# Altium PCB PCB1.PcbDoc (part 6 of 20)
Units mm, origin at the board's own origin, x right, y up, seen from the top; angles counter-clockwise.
Board outline 294.51 x 138.18 mm, 12 copper layers (Top Layer 1 _Signal, L2_GND, L3_Signals, L4_GND, L5_POWER, L6_Signals, L7_GND, L8_Signals, L9_GND, L10_POWER, L11_GND, Bottom Layer_Signals), stack 1.788 mm thick; 1254 components, 836 nets, 5699 pads, 2073 vias.
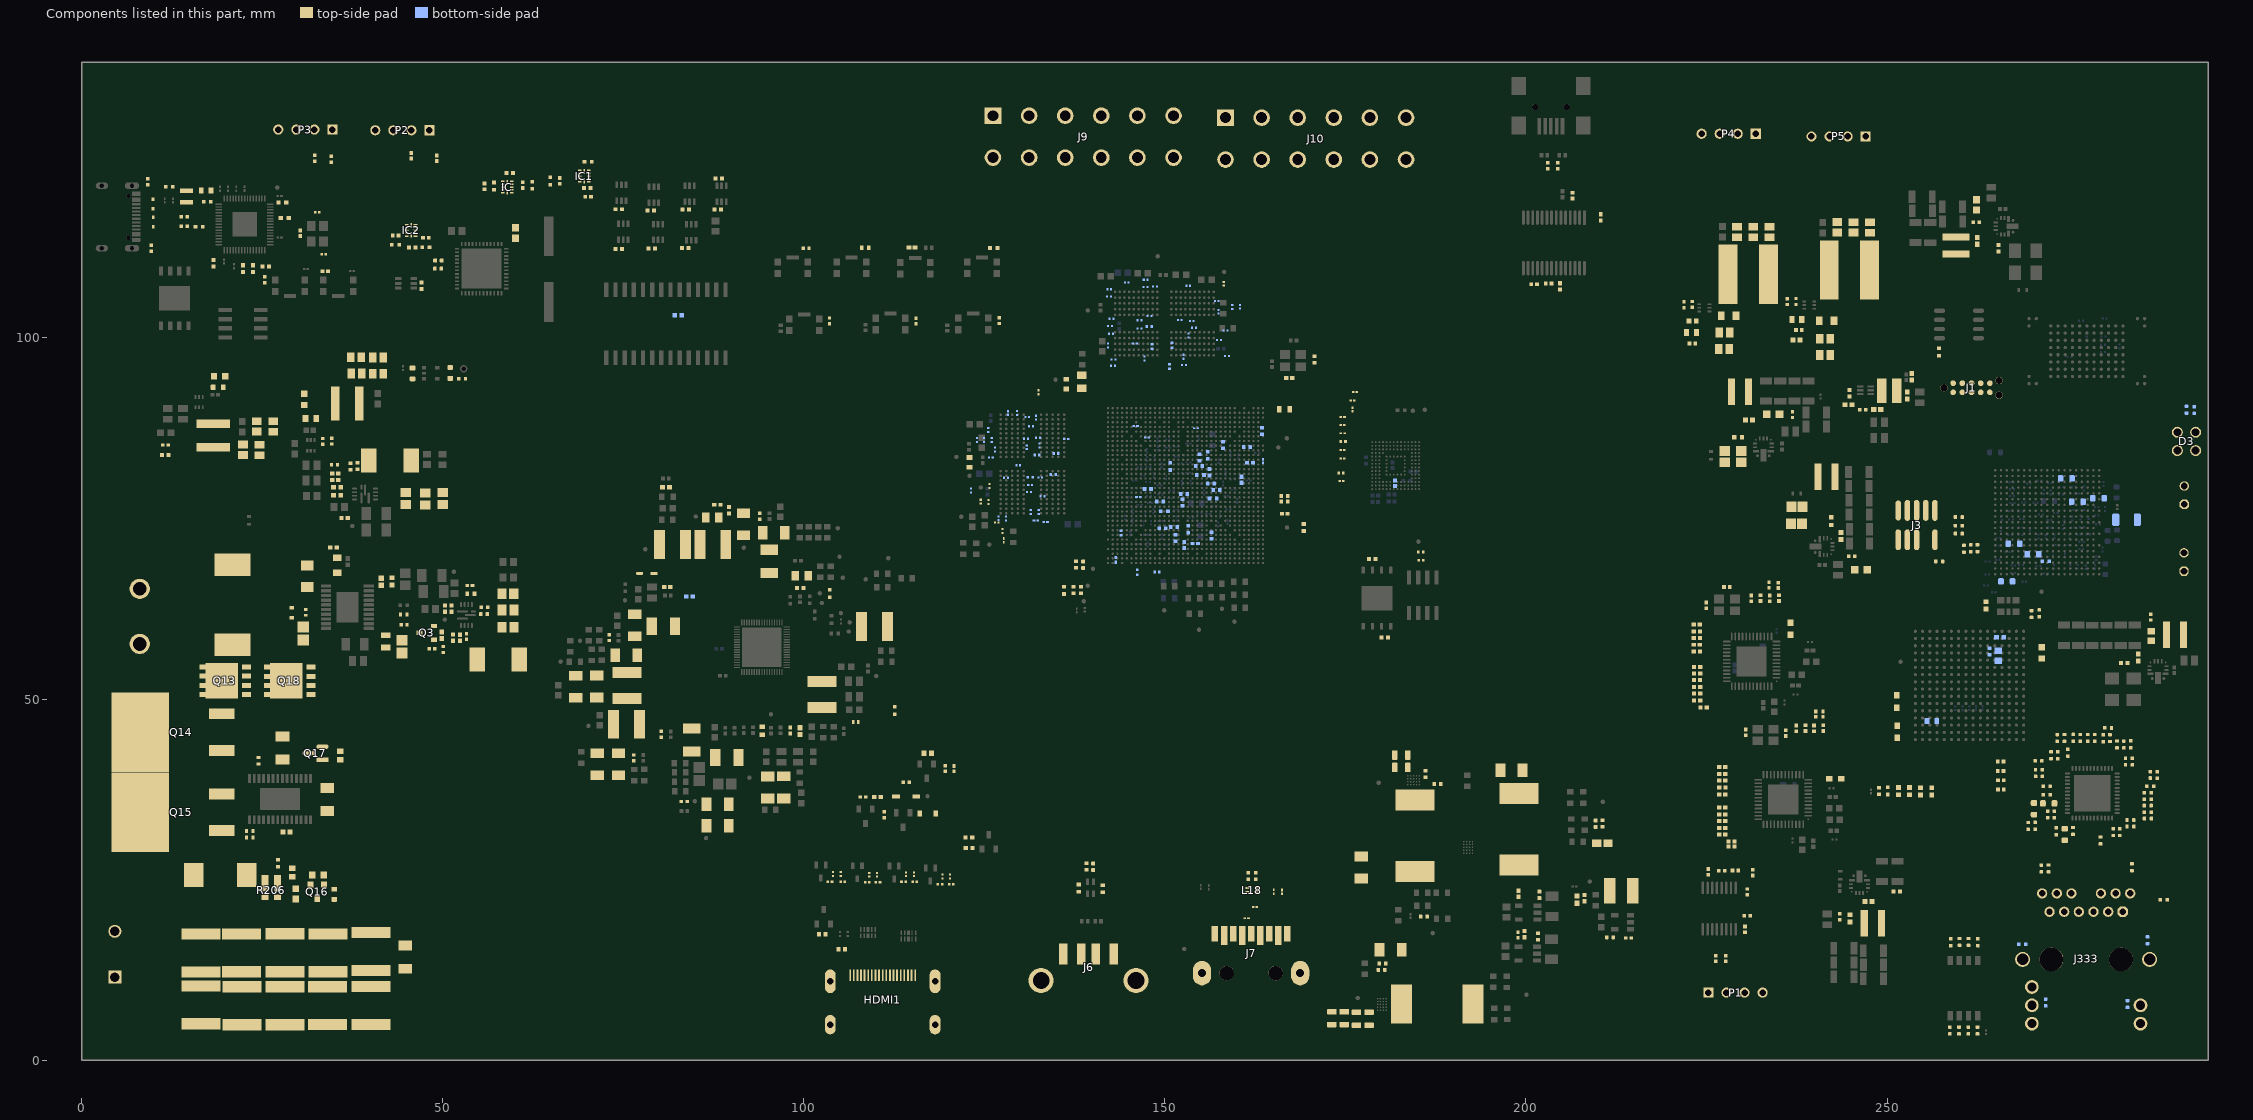
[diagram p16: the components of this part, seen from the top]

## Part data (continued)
C217: library part CMP-001-00011-6, "Chip Capacitor, 10 pF, +/- 0.25 pF, 50 V, 0402 (1005 Metric)", Capacitor Type=Ceramic, Case/Package=0402, Max Operating Temperature=125°C, Min Operating Temperature=-55°C, Tolerance=0.25%, Voltage Rating=50V
C218: library part CMP-2008-03481-1, "C0402C121G5GACTU", Manufacturer=Kemet
C219: library part CMP-2007-04689-1, Manufacturer="AVX Interconnect / Elco"
C220 C221 C230 C231 C232 C233 C249 C251 C252 C262 C263 C271 C272 C283 C289 C304 C309 C611 C627: library part CMP-001-00074-3, "10uF 6.3V X5R ±20% 0402 Multilayer Ceramic Capacitors MLCC - SMD/SMT ROHS", Case/Package=0402, LCSC=C76991, Max Operating Temperature=85°C, Min Operating Temperature=-55°C, Tolerance=10%, Voltage Rating=6.3V
C222 C239 C255 C264 C276 C306 C311 C463 C467 C542 C561 C567 C628: library part CMP-03422-000823-1, "10V 4.7uF X5R ±10% 0402 Multilayer Ceramic Capacitors MLCC - SMD/SMT ROHS", Capacitance="4.7 uF", LCSC=C326586, Manufacturer=YAGEO, Manufacturer Part Number=CC0402KRX5R6BB475, Package=CC0402, Temperature="-55°C to +125°C", Temperature Characteristic=X5R, Temperature Coefficient=30ppm/°C, Temperature Range High=+125°C, Temperature Range Low=-55°C, Tolerance=0.1, Voltage Rating="10 V"
C225: library part CMP-06035-026840-2, "CERAMIC CAP, MLCC 1UF 50VDC X5R"
C313 C369 C370 C371 C372 C374 C375 C376 C377 C378 C380 C381 C382 C383 C384 C385 C387 C389 C391: library part CAP1463, Manufacturer 1="TDK Corporation", Manufacturer 2="Taiyo Yuden", Manufacturer 3=Murata, Manufacturer 4=Yageo, Manufacturer Part Number 1=C1005X7R1H104K050BB, Manufacturer Part Number 2=UMK105B7104KV-FR, Manufacturer Part Number 3=GRM155R71H104KE14D, Manufacturer Part Number 4=CC0402KRX7R9BB104, Operating Temperature="-55C to +125C", Package=0402, Supplier Part Number 1=445-5932-1-ND, Temperature Coefficient=X7R, Tolerance=10%, Voltage=50V
C317 C318 C319 C320 C322 C323 C324 C327 C328 C331 C332 C333 C334 C335 C336 C337 C342 C344 C345 C346 C356 C357 C358 C359 C360 C361 C362 C363 C364 C365 C395 C396 C397 C398 C399 C400 C401 C403 C404 C405 C406 C407 C408 C409 C410 C411 C416 C417 C418 C419 C420 C421 C422 C423 C424 C425 C426 C427 C428 C429: library part CMP-03422-000955-1, "CC0201 100 nF X5R 20.00% 10 V", Capacitance="100 nF", Manufacturer=Yageo, Manufacturer Part Number=CC0201MRX5R6BB104, Package=CC0201-BA, Temperature="-55°C to +85°C", Temperature Characteristic=X5R, Temperature Coefficient=15%, Temperature Range High=+85°C, Temperature Range Low=-55°C, Tolerance=0.2, Voltage Rating="10 V"
C343 C352 C437 C488: library part CMP-06035-039918-1, "Chip Multilayer Ceramic Capacitors for General Purpose, 0805, 22uF, X5R, 15%, 20%, 10V / GRM21BR61A226ME44L", Capacitance=22uF, Case Code (Imperial)=0805, Case Code (Metric)=2012, Dielectric=X5R, Dielectric Material=Ceramic, Max Operating Temperature=85°C, Min Operating Temperature=-55°C, Package Quantity=3000, Tolerance=20%, Voltage=10V
C349 C351 C604 C605: library part CMP-08246-006695-1, "Multilayer Ceramic Capacitors 6.8μF ±10% 35V X5R SMD 0805 / C2012X5R1V685K125AC", Capacitance=6.8uF, Case Code (Imperial)=0805, Case Code (Metric)=2012, Dielectric Material=Ceramic, Max Operating Temperature=85°C, Min Operating Temperature=-55°C, Package Quantity=2000, Tolerance=10%, Voltage Rating=35V
C355: library part CMP-2008-04611-1, "GRM155R71C563KA88D", Manufacturer=Murata
C373 C379 C386 C390: library part CAP1207, Manufacturer 1=Murata, Manufacturer 2="TDK Corporation", Manufacturer Part Number 1=GRM155R60J475ME47D, Manufacturer Part Number 2=C1005X5R0J475M050BC, Operating Temperature="-55C to +85C", Package=0402, Supplier Part Number 1=490-5915-2-ND, Temperature Coeffcient=X5R, Tolerance=20%, Voltage=6.3V
C436 C445: library part CMP-001-00057-3, "Chip Capacitor, 220nF +/-20%, 10V, 0402, Thickness 0.6 mm", Case/Package=0402, LCSC=C47129, Max Operating Temperature=85°C, Min Operating Temperature=-55°C, Tolerance=10%, Voltage Rating=10V
C438 C447 C483 C484: library part CMP-06035-025383-1, "Chip Multilayer Ceramic Capacitors for General Purpose, 0805, 22uF, X5R, 15%, 20%, 16V", Capacitance=22uF, Case/Package=0805, Dielectric=X5R, Max Operating Temperature=85°C, Min Operating Temperature=-55°C, Package Quantity=10000, Tolerance=20%, Voltage Rating=16V
C439 C448: library part CMP-2008-04556-2, "CAP CER 1UF 10V X5R 0402", Capacitance=1uF, LCSC=C76999, Manufacturer=Murata, Manufacturer Part Number=GRM155R61A105KE15D, Package=GRM15-0.1, Temperature="-55°C to +85°C", Temperature Characteristic=X5R, Temperature Coefficient=15%, Temperature Range High=+85°C, Temperature Range Low=-55°C, Tolerance=10%, Voltage Rating=10V
C440 C441 C443 C449 C450 C452: library part CMP-2007-03222-3, "22uF 25V X5R ±20% 0805 Multilayer Ceramic Capacitors MLCC - SMD/SMT ROHS", Capacitance=22uF, Case Code (Imperial)=0805, Case Code (Metric)=2012, Dielectric=X5R, LCSC=C86816, Max Operating Temperature=85°C, Min Operating Temperature=-55°C, Package Quantity=3000, Resistor Type=Ceramic, Tolerance=20%, Voltage=25V
C451 C453: library part CMP-04427-002736-1, "General Purpose Ceramic Capacitor, 0402, 1uF, 20%, X5R, 15%, 16V", Capacitance=1uF, Case/Package=0402, Dielectric=X5R, Max Operating Temperature=85°C, Min Operating Temperature=-55°C, Package Quantity=10000, Tolerance=20%, Voltage Rating (DC)=16V
C474 C475 C476 C477 C478 C479 C480 C481: library part CMP-03422-000318-1, "CC0201 220 nF X5R 10.00% 10 V", Capacitance="220 nF", LCSC=C326658, Manufacturer=Yageo, Package=CC0201-BA, Temperature="-55°C to +85°C", Temperature Characteristic=X5R, Temperature Coefficient=15%, Temperature Range High=+85°C, Temperature Range Low=-55°C, Tolerance=0.1, Voltage Rating="10 V"
C482: library part CMP-2008-01233-1, LCSC=C2196193, Manufacturer=Vitramon, Part Number=VJ0402Y101KXAPW1BC
C485 C493 C500 C501 C509 C510: library part CMP-001-00081-4, "22uF 25V X5R ±20% 0805 Multilayer Ceramic Capacitors MLCC - SMD/SMT ROHS", Case/Package=0805, LCSC=C45783, Max Operating Temperature=85°C, Min Operating Temperature=-55°C, Tolerance=5%, Voltage Rating=16V
C499 C507 C516: library part CMP-001-00063-3, "Chip Capacitor, 1µF +/-20%, 10V, 0402, Thickness 0.6 mm", Case/Package=0402, LCSC=C14445, Max Operating Temperature=85°C, Min Operating Temperature=-55°C, Tolerance=10%, Voltage Rating=10V
C517: library part CMP-2008-01233-1, "100pF 50V X7R ±10% 0402 Multilayer Ceramic Capacitors MLCC - SMD/SMT ROHS", LCSC=C2196193, Manufacturer=Vitramon
C541 C543 C545 C546 C547 C548 C549 C550: library part CMP-2008-03082-2, "CAP CER 0.1UF 16V X7R 0402", Capacitance="0.10 μF", LCSC=C2167101, Manufacturer=Kemet, Manufacturer Part Number=C0402C104K4RACAUTO, Package=C0402-BB, Temperature="-55°C to +125°C", Temperature Characteristic=X7R, Temperature Coefficient=15%, Temperature Range High=+125°C, Temperature Range Low=-55°C, Tolerance=0.1, Voltage Rating="16 V"
C560 C563: library part CMP-03020-034488-1, "CAP CER 33PF 25V NP0 0201", Capacitance="33 pF", Manufacturer=KEMET, Manufacturer Part Number=C0201C330K3GACTU, Package=C0201-AB, Temperature="-55°C to +125°C", Temperature Characteristic=C0G, Temperature Coefficient=30ppm/°C, Temperature Range High=+125°C, Temperature Range Low=-55°C, Tolerance=0.1, Voltage Rating="25 V"
C575 C576 C577 C578 C579 C580 C581 C582 C583 C584: library part CMP-1042-00650-1, "CAP 470nF 200V ±10% 2220 (5750 Metric) Thickness 2.2mm SMD", Case-EIA=2220, LCSC=C49297048, Rated Voltage="200 V", Tolerance=20%
C585 C588 C589: library part CMP-1037-04727-1, "CAP 1uF 100V ±5% 1206 (3216 Metric) Thickness 1.9mm SMD", Case-EIA=1206, Case-Metric=3216, Rated Voltage="100 V", Tolerance=Â±5%
C586 C587: library part CMP-2006-03716-2, "CAP CER 1000PF 50V X7R 0603", Capacitance="1,000 pF", Manufacturer=KEMET, Manufacturer Part Number=C0603C102K5RACAUTO, Package=C0603C-CF, Temperature="-55°C to +125°C", Temperature Characteristic=X7R, Temperature Coefficient=30ppm/°C, Temperature Range High=+125°C, Temperature Range Low=-55°C, Tolerance=0.1, Voltage Rating="50 V"
C591: library part CMP-2006-02299-1, Manufacturer=Kemet, Part Number=C0603C104K4RAC7013
C593 C594 C595 C596 C607 C608 C609 C610 C630 C631 C633 C634: library part CMP-2008-03082-2, "CAP CER 0.1UF 16V X7R 0402", Capacitance="0.10 μF", Manufacturer=Kemet, Manufacturer Part Number=C0402C104K4RACAUTO, Package=C0402-BB, Temperature="-55°C to +125°C", Temperature Characteristic=X7R, Temperature Coefficient=15%, Temperature Range High=+125°C, Temperature Range Low=-55°C, Tolerance=0.1, Voltage Rating="16 V"
C598 C599 C606 C618: library part CMP-03020-010102-1, "C0402 15 pF X8R 10.00% 50 V", Capacitance="15 pF", LCSC=C2188232, Manufacturer=Kemet, Manufacturer Part Number=C0402C150K5HACAUTO, Package=C0402-BB, Temperature="-55°C to +125°C", Temperature Characteristic=X8R, Temperature Coefficient=15%, Temperature Range High=+125°C, Temperature Range Low=-55°C, Tolerance=0.1, Voltage Rating="50 V"
C619: library part CMP-2006-02217-1, Manufacturer=Kemet, Part Number=C0603C105M3RACTU
C641 C644 C645 C648 C683 C684: library part CMP-03020-014070-2, "CAP CER 0.1UF 25V X5R 0402", Capacitance="0.10 μF", Manufacturer=Kemet, Package=C0402, Temperature="-55°C to +125°C", Temperature Characteristic=X5R, Temperature Coefficient=15%, Temperature Range High=+125°C, Temperature Range Low=-55°C, Tolerance=0.2, Voltage Rating="25 V"
C642 C643 C646 C647 C685 C686: library part CMP-03422-000114-1, "CAP CER 1UF 25V X5R 0402", Capacitance="1 uF", Manufacturer=YAGEO, Manufacturer Part Number=CC0402KRX5R8BB105, Package=CC0402, Temperature="-55°C to +125°C", Temperature Characteristic=X5R, Temperature Coefficient=30ppm/°C, Temperature Range High=+125°C, Temperature Range Low=-55°C, Tolerance=0.1, Voltage Rating="25 V"
C667 C668 C675 C676: library part CMP-06035-005015-1, "Chip Multilayer Ceramic Capacitors for General Purpose, 0805, 10uF, X5R, 15%, 10%, 50V / GRM21BR61H106KE43K"
C669 C677: library part CMP-2000-07546-2, "Cap Ceramic 100nF 50V X7R 10% Pad SMD 0603 +125°C Automotive T/R / CGA3E2X7R1H104K080AA", Capacitance=100nF, Case Code (Imperial)=0603, Case Code (Metric)=1608, Dielectric=X7R, Max Operating Temperature=125°C, Min Operating Temperature=-55°C, Package Quantity=1, Ratings=AEC-Q200, Tolerance=10%, Voltage=50V
C670 C678: library part CMP-2008-03435-2, "CAP CER 56PF 10V NP0 0402 / C0402C560J8GACTU", Capacitance="56 pF", Manufacturer=Kemet, Manufacturer Part Number=C0402C560J8GACTU, Package=C0402-BB, Temperature="-55°C to +125°C", Temperature Characteristic=C0G, Temperature Coefficient=15%, Temperature Range High=+125°C, Temperature Range Low=-55°C, Tolerance=0.05, Voltage Rating="10 V"
C671 C672 C673 C679 C680 C681: library part CMP-06035-039918-1, "Chip Multilayer Ceramic Capacitors for General Purpose, 0805, 22uF, X5R, 15%, 20%, 10V", Capacitance=22uF, Case Code (Imperial)=0805, Case Code (Metric)=2012, Dielectric=X5R, Dielectric Material=Ceramic, Max Operating Temperature=85°C, Min Operating Temperature=-55°C, Package Quantity=3000, Tolerance=20%, Voltage=10V
CN1: library part DB910-7.62-2P, "-40℃~+105℃ 0.5~4 1 10~26 1x2P 2 21.8mm 2P 300V 30A 7.62mm Green M3 Through Hole Plugin,P=7.62mm Screw Terminal Blocks ROHS"
D1: library part CMP-08607-000062-1, "TVS DIODE 7V 10V 0402", Breakdown Voltage=9.8V, Capacitance=0.1pF, Clamping Voltage=10V, Manufacturer=Littelfuse, Package=SESD0402, Peak Pulse Current=2A, Reverse Standoff Voltage=7V, Temperature="-55°C to +125°C", Temperature Range High=+125°C, Temperature Range Low=-55°C
D2: library part CMP-07163-000040-1, "DIODE GEN PURP 75V 150MA SOD323F", Average Rectified Current=150mA, Forward Voltage=1V, Max Forward Surge Current (Ifsm)=2A, Max Operating Temperature=150°C, Max Repetitive Reverse Voltage (Vrrm)=75V, Min Operating Temperature=-55°C, Package Quantity=1, Peak Reverse Current=5uA, Power Dissipation=200mW
D3: library part DIODE1400, Forward Current=10mA, Manufacturer 1=Dialight, Manufacturer Part Number 1=5530123F, Package=553, Supplier Part Number 1=350-1823-ND
D4: library part CMP-1055-00467-1, "Schottky Barrier Diode, 2-Pin SOD-323, Pb-Free, Tape and Reel", Manufacturer="On Semiconductor"
D5 D6: library part CMP-027-000000-1, "Transient Voltage Suppressors for ESD Protection", Package=None
D7: library part CMP-004-00001-2, "-55℃~+125℃ 1.5A 1A 40V 600mV@1A Independent SOD-323 Schottky Diodes ROHS", Capacitance=-323f, Case/Package=SOD-323, Forward Current=150mA, Forward Voltage=1V, LCSC=C22624, Manufacturer=Fairchild, Max Operating Temperature=150°C, Min Operating Temperature=-55°C, Package Description="2-Pin Small Outline Diode Flat Lead, Body 1.7 x 1.25 mm", Package Quantity=3000, Peak Reverse Current=5uA
D9: library part CMP-14399-000014-1, "DIODE GEN PURP 100V 250MA SOD523"
D13: Case=SMC(DO-214AB)
FB1 FB3 FB4 FB5 FB6 FB24 FB25 FB26: library part IND1640, Manufacturer 1="TDK Corporation", Manufacturer Part Number 1=MPZ1608S121ATDH5, Operating Temperature="-55°C ~ 125°C", Package=0603, RMS Current=2A, Supplier Part Number 1=445-172891-1-ND, Test Frequency=100MHz
FB2: library part FB1007, Manufacturer 1=Murata, Manufacturer Part Number 1=BLM18PG330SN1D, Operating Temperature="-55C to +125C", Package=0603, Saturation Current=3A, Supplier Part Number 1=490-5220-1-ND, Test Frequency=100MHz
FB7: library part IND1986, Manufacturer 1=Murata, Manufacturer Part Number 1=BLM31KN121SZ1L, Operating Temperature="-55C to +125C", Package=1206, Saturation Current=6A, Supplier Part Number 1=490-16525-1-ND, Test Frequency=100MHz
FB9: library part CMP-0686-00554-8, "FERRITE BEAD 120 OHM 0603 1LN", Case Code (Imperial)=0603, Case Code (Metric)=1608, Current Rating=3A, DC Resistance (DCR)=30mR, Inductor Type="FERRITE BEAD", LCSC=C85831, Max Operating Temperature=125°C, Min Operating Temperature=-55°C, Package Quantity=4000, Test Frequency=100MHz, Tolerance=25%
HDMI1: library part HDMI-019S
IC IC1 IC2: "Voltage Level Translator Bidirectional 1 Circuit 4 Channel 50Mbps 12-XQFN _2x1.7_", Package="XQFN-12 NXP Semiconductors"
J1: library part CON1734, "CON TAG 10P TC2050 SMT", Manufacturer 1="Tag-Connect LLC", Manufacturer Part Number 1=TC2050-IDC-NL, Supplier Part Number 1=TC2050-IDC-NL-ND
J2 J34: library part CON1108, Manufacturer 1=FCI, Manufacturer 4=Samtec, Manufacturer 5=Sullins, Manufacturer 6="Würth Elektronik", Manufacturer 7="SPC Technology", Manufacturer 10="Shanghai NS-TECH", Manufacturer Part Number 1=68000-202HLF, Manufacturer Part Number 2=77311-118-02LF, Manufacturer Part Number 3=68001-202HLF, Manufacturer Part Number 4=TSW-102-07-G-S, Manufacturer Part Number 5=PBC02SAAN, Manufacturer Part Number 6=61300211121, Manufacturer Part Number 7=SPC20481, Manufacturer Part Number 8=TSW-102-07-F-S, Manufacturer Part Number 9=TSW-102-07-S-S, Manufacturer Part Number 10=NS-201-SH0100-1*2, Supplier Part Number 1=609-3502-ND
J3: library part CON2256, Current="3.4A per Contact", Manufacturer 1="Samtec Inc.", Manufacturer Part Number 1=FTSH-105-01-F-DV-007-K-P-TR, Operating Temperature="-55°C ~ 125°C", Supplier Part Number 1=SAM13926CT-ND
J5: library part CMP-009-00061-2
J6: library part CMP-1502-03240-3, "Wr-com; Right Angle Version 2.0; Connector SMT Socket, 30 V AC, 1.5A, 62900", Contact Resistance=20mΩ, Current Rating=1.5A, Insulation Resistance=1GΩ, Max Operating Temperature=105°C, Min Operating Temperature=-40°C, Operating Supply Voltage=30V
J7: library part CMP-1502-03220-3, "Conn USB 3.0 Type A RCP 9 POS 1.25mm Solder RA SMD 9 Terminal 1 Port T/R", Color=Blue, Contact Resistance=50mΩ, Current Rating=250mA, Flammability Rating="UL94 V-0", Insulation Resistance=100MΩ, Max Operating Temperature=85°C, Min Operating Temperature=-20°C, Operating Supply Voltage=30V
J8: library part CMP-2000-05797-1, "PC Terminal Block, Pitch 6.35 mm, 1 x 2 Position, Height 21.5 mm, Tail Lenght 5.1 mm, RoHS, Bulk", Manufacturer="Phoenix Contact", Package Description="PC Terminal Block, Pitch 6.35 mm, 1 x 2 Position, Height 21.5 mm, Tail Lenght 5.1 mm"
J9 J10: library part CMP-17439-000220-1, "XL Connector Wire to Board 12PIN", Current Rating=10A, Voltage Rating=150V
J333: library part CON2551, Manufacturer 1="Bel Fuse", Manufacturer Part Number 1=L829-1J1T-43, Operating Temperature="0°C ~ 70°C", Supplier Part Number 1=380-1110-ND
L1 L5 L11 L12: library part CMP-06042-016508-1, "FIXED IND"
L2 L3 L4 L7 L10 L13: library part CMP-14484-000922-1, "Inductor Power Shielded Wirewound 0.47uH 30% 100KHz Ferrite 5A 13mΩ DCR Automotive T/R", Case/Package=Nonstandard, Current Rating=5A, DC Resistance (DCR)=13mR, Inductance=470nH, Max Operating Temperature=125°C, Min Operating Temperature=-40°C, Package Quantity=500, Ratings=AEC-Q200, Resistor Type=Wirewound, Saturation Current=9A, Self Resonant Frequency=185MHz, Test Frequency=100kHz, Tolerance=30%
L6: library part CMP-11268-000050-1, "Fixed Inductors 2.2uH 20% 9.7A 14.5mOhms", DC Resistance (DCR)=14.5mR, Inductance=2.2uH, Max DC Current=9.2A, Max Operating Temperature=125°C, Min Operating Temperature=-40°C, Package Quantity=20, Self Resonant Frequency=38MHz, Test Frequency=100kHz, Tolerance=20%
L8 L15 L23 L24 L26: library part CMP-03913-66963829-3, "Inductor Power Shielded Wirewound 1uH 20% 100KHz Metal 10.1A 0.015Ohm DCR T/R Automotive AEC-Q200", Ambient Temperature Range High=85°C, Ambient Temperature Range Low=-40°C, Case/Package=SMD/SMT, Current Rating=7.2A, DC Resistance (DCR)=12mΩ, Inductance=1µH, Inductance Tolerance=20%, Max Operating Temperature=125°C, Saturation Current=9A, Self Resonant Frequency=55MHz, Test Frequency=100kHz
L9: library part CMP-03913-49216450-3, "Fixed Ind 1.5UH 3.7A 39 Mohm SMD", Ambient Temperature Range High=85°C, Ambient Temperature Range Low=-40°C, Case Code (Imperial)=1212, Case Code (Metric)=3030, Case/Package=SMD/SMT, Current Rating=3.7A, DC Resistance (DCR)=33mΩ, Inductance=1.5µH, Inductance Tolerance=20%, Max Operating Temperature=125°C, Saturation Current=4.5A, Self Resonant Frequency=51MHz, Test Frequency=100kHz
L14: library part CMP-11268-000050-1, "Fixed Inductors 2.2uH 20% 9.7A 14.5mOhms", DC Resistance (DCR)=14.5mR, Max DC Current=9.2A, Max Operating Temperature=125°C, Min Operating Temperature=-40°C, Package Quantity=20, Self Resonant Frequency=38MHz, Test Frequency=100kHz, Tolerance=20%
L16 L17: library part SMMS0650-1R5M
L18: library part CMP-08256-000021-1, "CMC 100MA 2LN 90 OHM SMD"
L19 L20 L21: library part CMP-0226-00096-3, "INDUCTOR, 0.22UH, 27A, 20%; Product Range: WURTH ELEKTRONIK - WE-HCC Series; Indu", Ambient Temperature Range High=75°C, Ambient Temperature Range Low=-40°C, Case/Package=Nonstandard, Current Rating=27A, DC Resistance (DCR)=1.1mΩ, Inductance Tolerance=20%, LCSC=C2047999, Max Operating Temperature=125°C, Saturation Current=82.9A, Self Resonant Frequency=280MHz, Series Resistance=530µΩ, Test Frequency=100kHz
L22: library part LVF404026-2R2M-N
L25: library part CMP-14484-000214-1, "SMD Inductors 3.3uH ±20% 0.8A 0.26Ω 0806", Case Code (Imperial)=0806, Case Code (Metric)=2016, Current Rating=800mA, DC Resistance (DCR)=260mR, Inductance=3.3uH, Max DC Current=400mA, Max Operating Temperature=105°C, Min Operating Temperature=-40°C, Package Quantity=2000, Resistor Type=Wirewound, Self Resonant Frequency=55MHz, Test Frequency=7.96MHz, Tolerance=20%
L27 L28: library part CMP-2000-07144-1, "Semi-Shielded Power Inductor, 2.2 uH, +/- 30%, 6.3 A, -40 to 125 degC, 2-Pin SMD, RoHS, Tape and Reel", Current, Rating=6.3A, Inductance=2.2μH, Manufacturer=Bourns, Package Description="2-Pin Surface Mounted Device, Body 8 x 8 mm", Package Reference=SRN8040, Tolerance=±30%
L29: library part CMP-07248-000022-1, "FIXED IND 1.8UH 24A 4.0 MOHM SMD", Inductance=1.8uH, Manufacturer=Bourns, Package=SRP1265A, RMS Current=24A, Saturation Current=40A, Self Resonant Frequency=30MHz, Series Resistance=4mΩ, Temperature="-40°C to +150°C", Temperature Range High=+150°C, Temperature Range Low=-40°C, Test Frequency=100kHz, Tolerance=20%
P1 P2 P3 P4 P5: library part CMP-002-00034-2, "Male Header, Pitch 2.5 mm, 1 x 4 Position, Height 6.1 mm, Tail Length 3.4 mm, -25 to 85 degC, RoHS, Bulk", Manufacturer=JST, Max Operating Temperature=85°C, Min Operating Temperature=-25°C, Package Description="XH Series Disconnectable Crimp Style Connector, Pitch 2.5 mm, 1 x 4 Position, Height 6.1 mm, Tail Length 3.4 mm"
Q3: library part CMP-20235-000001-1, "NPN TRANSISTOR 1.5A 40V SOT-23 R", Case/Package=TO-236-3, Collector Emitter Breakdown Voltage=25V, Collector Emitter Voltage (VCEO)=400mV, Max Collector Current=1.5A, Max Power Dissipation=300mW, Transition Frequency=100MHz
Q13 Q18: "-55℃~+175℃ 1 N-channel 1.9V 2.6mΩ 205A 20pF 3.8W 4.23nF 41nC@10V 60V 808pF N-Channel VSON-8(5x6) MOSFETs ROHS", Package=VSON-8(5x6)
Q14 Q15: library part PSMN4R8-100BSEJ-VB, "PSMN4R8-100BSEJ-VB", Case/Package=TO-263(D2PAK)
Q16: library part CMP-2000-04929-2, "MOSFET N-CH 60V 115MA SOT23-3", Case/Package=SOT-23, Continuous Drain Current (ID)=115mA, Drain to Source Breakdown Voltage=70V, Drain to Source Resistance=7.5R, Drain to Source Voltage (Vdss)=60V, Gate to Source Voltage (Vgs)=20V, Input Capacitance=50pF, Max Operating Temperature=150°C, Max Power Dissipation=300mW, Min Operating Temperature=-55°C, Package Quantity=3000, Power Dissipation=540mW, Threshold Voltage=2.5V
Q17: library part CMP-2000-04931-2, "TRANS NPN 40V 0.2A SMD SOT23-3", Case/Package=SOT-23, Collector Base Voltage (VCBO)=60V, Collector Emitter Breakdown Voltage=40V, Collector Emitter Saturation Voltage=300mV, Continuous Collector Current=200mA, Emitter Base Voltage (VEBO)=6V, Frequency=300MHz, Max Operating Temperature=150°C, Max Power Dissipation=300mW, Min Operating Temperature=-55°C, Package Quantity=3000, Power Dissipation=350mW
R1 R4 R5 R6 R7 R8 R16 R17 R18 R19 R42 R339 R374 R376 R381 R383 R385 R387 R389 R391 R395: library part RSMT1019, Manufacturer 1=Panasonic, Manufacturer Part Number 1=ERJ-2RKF1002X, Operating Temperature="-55C to +155C", Package=0402, Power=1/10W, Supplier Part Number 1=P10.0KLCT-ND, Temperature Coeffcient=100ppm/C, Tolerance=1%, Voltage=50V
R2: library part CMP-2002-02548-2, "RES SMD 10 OHM 1% 1/16W 0402", Manufacturer=Yageo, Manufacturer Part Number=RT0402FRE0710RL, Package=RT0402, Power Rating=0.063W, Resistance=10Ω, Temperature="-55°C to +155°C", Temperature Coefficient="50 ppm/°C", Temperature Range High=+155°C, Temperature Range Low=-55°C, Tolerance=0.01, Voltage Rating=50V
R3 R130: library part CMP-03211-001392-1, "SMD Precision Pulse Thick Film Chip Resistor", Manufacturer=TE, Manufacturer Part Number=CRGP0402F100K, Package=CRGP0402, Power Rating=0.125W, Resistance=100KΩ, Temperature="-55°C to +155°C", Temperature Coefficient=±100ppm/°C, Temperature Range High=+155°C, Temperature Range Low=-55°C, Tolerance=0.01, Voltage Rating=50V
R9 R56 R57 R58 R59 R60 R61 R62 R63 R64 R70 R92 R95 R96 R97: library part CMP-26527-001890-1, "-55℃~+155℃ 0Ω 25V 50mW Thick Film Resistor 0201 Chip Resistor - Surface Mount ROHS", Case Code (Imperial)=0201, Case Code (Metric)=0603, LCSC=C2479117, Max Operating Temperature=125°C, Max Power Dissipation=50mW, Min Operating Temperature=-55°C, Package Quantity=10000, Resistance=0R, Resistor Type="Thick Film"
R10 R12 R13 R15 R21 R22 R375 R377 R382 R384 R386 R388 R390 R392 R393 R394 R396 R397: library part RES1022, Manufacturer 1=Panasonic, Manufacturer Part Number 1=ERJ-2RKF1001X, Operating Temperature="-55C to +155C", Package=0402, Power=1/10W, Supplier Part Number 1=P1.00KLTR-ND, Temperature Coefficient=100ppm/C, Tolerance=1%, Voltage=50V
R11 R14 R400: library part RSMT1040, Manufacturer 1=Yageo, Manufacturer 2="Stackpole Electronics Inc", Manufacturer Part Number 1=RC0402JR-070RL, Manufacturer Part Number 2=RMCF0402ZT0R00, Operating Temperature="-55C to +155C", Package=0402, Power=1/16W, Supplier Part Number 1=311-0.0JRCT-ND
R20: library part CMP-1011-00124-1, "120K 0.063W 5% 0402 (1005 Metric)  SMD", Case-EIA=0402, Case-Metric=1005, Power="0.063 W", Tolerance="5 %"
R23 R81: library part CMP-2002-08016-1, LCSC=C137861, Manufacturer=Yageo, Part Number=RC0402JR-07510KL
R24 R25 R26 R305 R306: library part CMP-009-00082-2, "22R 0.063W 5% 0402 (1005 Metric)  SMD", Case/Package=0402, LCSC=C25092, Power=63mW, Tolerance=5%
R27 R150 R151 R152 R153 R154 R155 R156: library part CMP-03412-044155-1, "Anti-Sulfurated Chip Resistors Automotive Grade 49.9Ω 1% 200ppm/°C 0201", Case/Package=0201, Max Operating Temperature=125°C, Max Power Dissipation=50mW, Min Operating Temperature=-55°C, Resistance=49.9R, Resistor Type="Thick Film", Temperature Coefficient=200ppm/°C, Tolerance=1%
R28 R29 R34 R36 R38 R177 R179 R181 R183: library part CMP-02407-010762-1, "RES SMD 1.2K OHM 1% 1/10W 0402", Case Code (Imperial)=0402, Case Code (Metric)=1005, Max Operating Temperature=175°C, Max Power Dissipation=100mW, Min Operating Temperature=-55°C, Package Quantity=1, Resistance=100R, Temperature Coefficient=50ppm/°C, Tolerance=1%, Voltage Rating=50V
R30 R31 R263: library part CMP-03412-047152-1, "Anti-Sulfurated Chip Resistor Automotive Grade 0Ω Jumper 0.125W 0805", Case Code (Imperial)=0805, Case Code (Metric)=2012, Max Operating Temperature=155°C, Max Power Dissipation=125mW, Min Operating Temperature=-55°C, Package Quantity=5000, Resistance=0R, Resistor Type="Thick Film"
R32: library part CMP-2002-07855-1, Manufacturer=Yageo, Part Number=RC0402FR-13120KL
R33 R37: library part CMP-03211-001392-1, "100k 0402", Manufacturer=TE, Manufacturer Part Number=CRGP0402F100K, Package=CRGP0402, Power Rating=0.125W, Resistance=100KΩ, Temperature="-55°C to +155°C", Temperature Coefficient=±100ppm/°C, Temperature Range High=+155°C, Temperature Range Low=-55°C, Tolerance=0.01, Voltage Rating=50V
R35: library part CMP-2002-05709-1, "20k 0402 1%", Manufacturer="TE Connectivity / AMP", Part Number=CRG0402F20K
R39 R40: library part CMP-03412-037959-1, "RES 200kΩ ±5% 0.063W 0402", Case Code (Imperial)=0402, Case Code (Metric)=1005, Max Operating Temperature=155°C, Max Power Dissipation=63mW, Min Operating Temperature=-55°C, Power Rating=62.5mW, Resistance=200kR, Resistor Type="Thick Film", Temperature Coefficient=100ppm/°C, Tolerance=5%, Voltage Rating=50V
R41 R72 R73 R128 R172 R196 R203 R272 R276 R278 R279 R280 R281 R282 R284 R285: library part CMP-2002-01682-1, Manufacturer="Vishay BCcomponents", Part Number=TNPW040210K0DEED
R43: library part CMP-2002-08310-2, "RES Thick Film, 1.82kΩ, 1%, 0.063W, 100ppm/°C, 0402 / CRCW04021K82FKED", Case Code (Imperial)=0402, Case Code (Metric)=1005, Max Operating Temperature=155°C, Max Power Dissipation=63mW, Min Operating Temperature=-55°C, Package Quantity=10, Resistance=1.82kR, Temperature Coefficient=100ppm/°C, Tolerance=5%, Voltage Rating=50V
R44 R45 R48 R49: library part CMP-2004-00015-1, Manufacturer="Vishay Dale", Part Number=CRCW020110K0FKED
R46 R47 R51 R71 R274 R275 R303: library part CMP-26527-006303-1, "240Ω ±1% 0.05W 0201 Thick Film Chip Resistor AEC-Q200 compliant", Case Code (Imperial)=0201, Case Code (Metric)=0603, Max Operating Temperature=125°C, Max Power Dissipation=50mW, Min Operating Temperature=-55°C, Resistance=240R, Resistor Type="Thick Film", Temperature Coefficient=200ppm/°C, Tolerance=1%
R50 R160 R161 R185 R232: library part CMP-2002-03043-1, "10KR  / CRCW040210K0FKEDHP", Manufacturer="Vishay Dale", Part Number=CRCW040210K0FKEDHP
R52 R157 R162 R186 R233: library part CMP-2002-00056-2, "RES Thick Film, 4.87kΩ, 1%, 0.063W, 100ppm/°C, 0402 / CRCW04024K87FKED", Case Code (Imperial)=0402, Case Code (Metric)=1005, Max Operating Temperature=155°C, Max Power Dissipation=63mW, Min Operating Temperature=-55°C, Package Quantity=10, Resistance=4.87kR, Temperature Coefficient=100ppm/°C, Tolerance=1%, Voltage Rating=50V
R53 R159 R163: library part CMP-2002-08161-1, "Resistance = 11.5 kΩ / Tolerance = 1.0% / Power = 63 mW / CRCW040211K5FKED", Manufacturer="Vishay Dale", Part Number=CRCW040211K5FKED
R54: library part CMP-26527-000161-1, "1.21kΩ ±1% 0.1W 0603 Thick Film Chip Resistor AEC-Q200 compliant / RMCF0603FG1K21", Case/Package=0603, Max Operating Temperature=155°C, Max Power Dissipation=100mW, Min Operating Temperature=-55°C, Resistance=1.21kR, Resistor Type="Thick Film", Temperature Coefficient=100ppm/°C, Tolerance=1%
R55 R140 R146: library part CMP-2002-08123-3, "RES Thick Film, 100kΩ, 1%, 0.063W, 100ppm/°C, 0402", Case Code (Imperial)=0402, Case Code (Metric)=1005, Max Operating Temperature=155°C, Max Power Dissipation=63mW, Min Operating Temperature=-55°C, Package Quantity=10000, Resistance=100kR, Temperature Coefficient=100ppm/°C, Tolerance=1%, Voltage Rating=50V
R65 R67: library part CMP-03412-006200-1, "RT0201 10KΩ 0.05W 50 ppm/°C 0.10%", Manufacturer=Yageo, Package=RT0201, Power Rating=0.05W, Resistance=10KΩ, Temperature="-55°C to +125°C", Temperature Coefficient="50 ppm/°C", Temperature Range High=+125°C, Temperature Range Low=-55°C, Tolerance=0.001, Voltage Rating=25V
R66: library part CMP-03211-008081-1, "CRGCQ 0402 10K 5%", Ambient Temperature Range High=+70°C, Manufacturer="TE Connectivity", Manufacturer Part Number=CRGCQ0402J10K, Package=CRGCQ0402, Power Rating=0.0625W, Resistance=10KΩ, Temperature="-55°C to +155°C", Temperature Coefficient=±100ppm/°C, Temperature Range High=+155°C, Temperature Range Low=-55°C, Tolerance=0.05, Voltage Rating=50V
R68: library part CMP-009-00082-2, "22R 0.063W 5% 0402 (1005 Metric)  SMD", Case/Package=0402, Power=63mW, Tolerance=5%
R69: library part CMP-009-00103-2, "47K5 0.063W 1% 0402 (1005 Metric)  SMD", Case/Package=0402, Power=63mW, Tolerance=1%
R74 R175: library part CMP-03412-048355-1, "Anti-Sulfurated Chip Resistors Automotive Grade 0Ω 0402", Case Code (Imperial)=0402, Case Code (Metric)=1005, Max Operating Temperature=155°C, Min Operating Temperature=-55°C, Package Quantity=10000, Resistance=0R, Resistor Type="Thick Film", Tolerance=5%
R75 R79 R80 R83 R85 R86 R122 R125 R134 R135: library part CMP-2002-07343-1, LCSC=C60491, Manufacturer="Yageo / Phycomp", Part Number=RC0402FR-07100KL
R76: library part CMP-2002-03447-1, Manufacturer="TE Connectivity / AMP", Part Number=CPF0402B30KE1
R77: library part CMP-2002-08387-1, Manufacturer="Vishay Dale", Part Number=CRCW0402232KFKED
R78 R82: library part CMP-009-00098-2, "3R3 0.063W 5% 0402 (1005 Metric)  SMD", Case/Package=0402, LCSC=C25165, Power=63mW, Tolerance=5%
R84: library part CMP-03412-011926-2, "RES 43kΩ ±1% 0.063W 0402", Case/Package=0402, LCSC=C227081, Max Operating Temperature=155°C, Max Power Dissipation=63mW, Min Operating Temperature=-55°C, Resistance=43kR, Resistor Type="Thick Film", Temperature Coefficient=100ppm/°C, Tolerance=1%
R87 R89 R107 R114 R127 R133: library part CMP-2002-07353-1, "-55℃~+155℃ 10kΩ 50V 62.5mW Thick Film Resistor ±1% ±100ppm/℃ 0402 Chip Resistor - Surface Mount ROHS", LCSC=C60490, Manufacturer="Yageo / Phycomp", Part Number=RC0402FR-0710KL
R88: library part CMP-1011-00609-2, LCSC=C137934, Manufacturer="Yageo / Phycomp", Part Number=RC0402FR-077K5L
R90: library part CMP-009-00000-5, "Chip Resistor, 51 KOhm, +/- 5%, 0.063 W, -55 to 155 degC, 0402 (1005 Metric)", Case/Package=0402, LCSC=C107230, Max Operating Temperature=155°C, Min Operating Temperature=-55°C, Power=63mW, Tolerance=5%
R91 R104 R176: library part CMP-03412-012162-1, "RES SMD 200 OHM 0.5% 1/20W 0201", LCSC=C852273, Manufacturer=Yageo, Manufacturer Part Number=RT0201DRD07200RL, Package=RT0201, Power Rating=0.05W, Resistance=200Ω, Temperature="-55°C to +125°C", Temperature Coefficient="25 ppm/°C", Temperature Range High=+125°C, Temperature Range Low=-55°C, Tolerance=0.005, Voltage Rating=25V
R93 R94 R173 R174: library part CMP-009-00088-2, "2R2 0.063W 5% 0402 (1005 Metric)  SMD", Case/Package=0402, LCSC=C100632, Power=63mW, Tolerance=5%
R98: library part CMP-2004-01521-1, LCSC=C172779, Manufacturer="KOA Speer", Part Number=RK73H1HTTC8201F
R99: library part CMP-2004-00919-1, Manufacturer="Vishay Dale", Part Number=CRCW02018K20FKED
R100 R102 R105: library part CMP-02407-007381-1, "RES Thick Film, 47kΩ, 1%, 0.063W, 100ppm/°C, 0402", Case/Package=0402, LCSC=C4063497, Max Operating Temperature=155°C, Max Power Dissipation=63mW, Min Operating Temperature=-55°C, Package Quantity=50000, Resistance=47kR, Temperature Coefficient=100ppm/°C, Tolerance=1%
R101: library part RES3010, Manufacturer 1="Vishay Dale", Manufacturer Part Number 1=CRCW040210R0FKEDC, Operating Temperature="-55C to +155C", Package=0402, Power=1/16W, Supplier Part Number 1=541-3964-2-ND, Temperature Coefficient=100ppm/C, Tolerance=1%
R103: library part CMP-04015-066543-1, "1.2kΩ ±1% 0.063W, 1/16W Chip Resistor 0402 (1005 Metric) Moisture Resistant Thin Film", LCSC=C2499765
R106 R108: library part CMP-04015-046155-1, "1.8kΩ ±0.1% 0.063W, 1/16W Chip Resistor 0402 (1005 Metric) Moisture Resistant Thin Film", LCSC=C4121753
R109 R110 R111 R112 R115 R116 R117 R118: library part CMP-1010-00390-1, "590R 0.05W 1% 0201 (0603 Metric)  SMD", Case-EIA=0201, Case-Metric=0603, LCSC=C320976, Power="0.05 W", Tolerance="1 %"
R113: library part CMP-03412-047873-1, "RES 1kΩ ±1% 0.063W 0402", LCSC=C4270447
R119: library part CMP-03412-041263-1, "RES 27kΩ ±1% 0.125W 0402"
R120 R121 R124: library part CMP-009-00065-2, "100R 0.063W 1% 0402 (1005 Metric)  SMD", Case/Package=0402, LCSC=C25076, Power=63mW, Tolerance=1%
R123 R129: library part CMP-009-00068-2, "120K 0.063W 1% 0402 (1005 Metric)  SMD", Case/Package=0402, LCSC=C25750, Power=63mW, Tolerance=1%
R131 R132: library part CMP-009-00105-2, "4K7 0.063W 1% 0402 (1005 Metric)  SMD", Case/Package=0402, LCSC=C25900, Power=63mW, Tolerance=1%
R136: library part CMP-1659-00037-1, "Chip Resistor, 220 KOhm, +/- 1%, 100 mW, -55 to 155 degC, 0603 (1608 Metric), RoHS, Tape and Reel", Max Operating Temperature="70 degC", Min Operating Temperature="-25 degC", Resistance="0.1 Ohm"
R137: library part CMP-2002-08248-1, "CRCW040217K4FKED", Manufacturer="Vishay Dale"
R138 R144: library part CMP-03412-049842-1, "Thin Film Chip Resistors Automotive Grade 30kΩ 1% 50ppm/°C 0603"
R139 R141 R143: library part CMP-2002-03043-1, "CRCW040210K0FKEDHP", Manufacturer="Vishay Dale"
R142: library part CMP-1011-00718-3, "RES Thick Film, 68.1kΩ, 1%, 0.063W, 100ppm/°C, 0402", Case Code (Imperial)=0402, Case Code (Metric)=1005, Max Operating Temperature=155°C, Max Power Dissipation=63mW, Min Operating Temperature=-55°C, Package Quantity=10, Resistance=68.1kR, Resistance Tolerance=1%, Resistor Type="Thick Film", Temperature Coefficient=100ppm/°C, Voltage Rating=50V
R145: library part CMP-009-00063-2, "-55℃~+155℃ 100mW 135kΩ 75V Thin Film Resistor ±0.1% ±25ppm/℃ 0603 Chip Resistor - Surface Mount ROHS", Case/Package=0603
R147: library part CMP-2002-08356-2, "RES Thick Film, 20kΩ, 1%, 0.063W, 100ppm/°C, 0402", Case Code (Imperial)=0402, Case Code (Metric)=1005, Max Operating Temperature=155°C, Max Power Dissipation=63mW, Min Operating Temperature=-55°C, Package Quantity=10, Resistance=20kR, Temperature Coefficient=100ppm/°C, Tolerance=1%, Voltage Rating=50V
R148 R247 R286 R288 R290 R292: library part CMP-009-00002-5, "DNP", Case/Package=1206, Max Operating Temperature=155°C, Min Operating Temperature=-55°C, Power=250mW, Tolerance=5%, Voltage Rating=200V
R149 R248 R287 R289 R291 R293 R307 R308 R309: library part CMP-009-00002-5, "10mΩ 1W Current Sense Resistor SMD ±1% ±100ppm/℃ 1206 Current Sense Resistors / Shunt Resistors ROHS", Case/Package=1206, Max Operating Temperature=155°C, Min Operating Temperature=-55°C, Power=1W, Tolerance=5%, Voltage Rating=200V
R158: library part CMP-2000-03504-1, "CRCW0603604RFKEA / Resistance = 604 Ω / Tolerance = 1.0% / Power = 100 mW", Manufacturer="Vishay Dale", Part Number=CRCW0603604RFKEA
R164 R165: library part CMP-2002-06970-1, "-55℃~+155℃ 0Ω 62.5mW Thick Film Resistor ±5% 0402 Chip Resistor - Surface Mount ROHS", Manufacturer=Yageo, Part Number=RC0402JR-100RL
R166 R167 R168 R169 R170 R171 R198 R199 R201 R202: library part CMP-02407-004337-1, "RES Thick Film, 22Ω, 1%, 0.063W, 100ppm/°C, 0402", Case/Package=0402, LCSC=C4191401, Max Operating Temperature=155°C, Max Power Dissipation=63mW, Min Operating Temperature=-55°C, Package Quantity=50000, Resistance=22R, Temperature Coefficient=100ppm/°C, Tolerance=1%
R178: library part CMP-03412-044565-1, "Thin Film Chip Resistors Automotive Grade 3kΩ 1% 50ppm/°C 0402", Case/Package=0402
R180: library part CMP-03412-047267-1, "RES 6.8kΩ ±5% 0.125W 0402", Case/Package=0402
R182: library part CMP-02407-010136-1, "RES Thick Film, 12kΩ, 1%, 0.063W, 100ppm/°C, 0402", Case/Package=0402, Max Operating Temperature=155°C, Max Power Dissipation=63mW, Min Operating Temperature=-55°C, Package Quantity=50000, Resistance=12kR, Temperature Coefficient=100ppm/°C, Tolerance=1%
R184 R231: library part CMP-2000-04117-2, "RES 6.04K OHM 1% 1/10W 0603 / RC0603FR-076K04L", Case Code (Imperial)=0603, Case Code (Metric)=1608, Max Operating Temperature=155°C, Max Power Dissipation=100mW, Min Operating Temperature=-55°C, Resistance=6.04kR, Resistor Type="Thick Film", Temperature Coefficient=100ppm/°C, Tolerance=1%, Voltage Rating=50V
R187: library part CMP-2002-06970-1, Manufacturer=Yageo, Part Number=RC0402JR-100RL
R188: library part CMP-03412-046795-1, "Anti-Sulfurated Chip Resistors Automotive Grade 33Ω 1% 100ppm/°C 0603", Case/Package=0603, Max Operating Temperature=155°C, Max Power Dissipation=100mW, Min Operating Temperature=-55°C, Resistance=33R, Resistor Type="Thick Film", Temperature Coefficient=100ppm/°C, Tolerance=1%
R189 R216 R217 R218 R219 R220 R221 R222 R223 R224 R225 R226 R227 R236 R237 R238 R239 R240 R241 R243 R244 R245 R246: library part CMP-2002-06970-1, Manufacturer=Yageo
R190 R192: library part CMP-04015-008529-1, "5.1kΩ ±1% 0.063W, 1/16W Chip Resistor 0402 (1005 Metric) Moisture Resistant Thin Film", Case/Package=0402
R191 R193: library part CMP-03412-039875-1, "Anti-Sulfurated Chip Resistors Automotive Grade 51Ω 5% 100ppm/°C 0402", Case/Package=0402, Max Operating Temperature=155°C, Max Power Dissipation=63mW, Min Operating Temperature=-55°C, Resistance=51R, Resistor Type="Thick Film", Temperature Coefficient=100ppm/°C, Tolerance=5%
R194 R195: library part CMP-04015-026447-1, "3.3kΩ ±1% 0.063W, 1/16W Chip Resistor 0402 (1005 Metric) Moisture Resistant Thin Film"
R197: library part CMP-2002-02445-2, "RES SMD 1.2K OHM 1% 1/10W 0402", Case/Package=0402, Max Operating Temperature=125°C, Max Power Dissipation=63mW, Min Operating Temperature=-55°C, Package Quantity=10000, Resistance=1kR, Temperature Coefficient=25ppm/°C, Tolerance=0.1%
R200 R204: library part CMP-03211-006314-1, "CRGCQ0402 1KΩ 1% ±100ppm/°C 50V", Ambient Temperature Range High=+70°C, Manufacturer="TE Connectivity", Manufacturer Part Number=CRGCQ0402F1K0, Package=CRGCQ0402, Power Rating=0.0625W, Resistance=1KΩ, Temperature="-55°C to +155°C", Temperature Coefficient=±100ppm/°C, Temperature Range High=+155°C, Temperature Range Low=-55°C, Tolerance=0.01, Voltage Rating=50V
R205 R207: library part CMP-1011-00250-1, "4R99 0.063W 1% 0402 (1005 Metric)  SMD", Case-EIA=0402, Case-Metric=1005, Power="0.063 W", Tolerance="1 %"
R206: library part CMP-03412-024484-1, "METAL CURRECT SENSOR 4 TERMINATI", Manufacturer=Yageo, Manufacturer Part Number=PS0612FKF070R001L, Package=PS0612, Power Rating=1W, Resistance=1mΩ, Temperature="-55°C to +150°C", Temperature Coefficient=100ppm/°C, Temperature Range High=+150°C, Temperature Range Low=-55°C, Tolerance=1%
R208: library part CMP-250906-284575-1, "RES Thin Film,  100kΩ, 0.1%, 0.1W, 25ppm/°C, 0603"
R209: library part CMP-03211-000534-1, "RP73P 0402 95.3KΩ 0.1W 25ppm/°C 0.10% 50V", Manufacturer="TE Connectivity", Manufacturer Part Number=RP73PF1E95K3BTDF, Package=RP73P-1E, Power Rating=0.1W, Resistance=95.3KΩ, Temperature="-55°C to +155°C", Temperature Coefficient=25ppm/°C, Temperature Range High=+155°C, Temperature Range Low=-55°C, Tolerance=0.10%, Voltage Rating=50V
R210: library part CMP-009-00063-2, "Jumper 0603 (1608 Metric)", Case/Package=0603
R211: library part CMP-13261-005100-1, "Res Thick Film 0402 8.87kΩ 1% 0.063W ±100ppm/°C Molded SMD T/R", Case Code (Imperial)=0402, Case Code (Metric)=1005, Max Operating Temperature=155°C, Max Power Dissipation=63mW, Min Operating Temperature=-55°C, Package Quantity=1, Resistance=8.87kR, Temperature Coefficient=100ppm/°C, Tolerance=1%, Voltage Rating (DC)=50V
R212: library part CMP-1011-00672-1, "28K 0.063W 1% 0402 (1005 Metric)  SMD", Case-EIA=0402, Case-Metric=1005, Power="0.063 W", Tolerance="1 %"
R213: library part CMP-1012-00736-1, "100K 0.1W 1% 0603 (1608 Metric)  SMD", Case-EIA=0603, Case-Metric=1608, Power="0.1 W", Tolerance="1 %"
R214: library part CMP-2002-03111-1, Manufacturer="TE Connectivity / AMP", Part Number=8-1879061-0
R215 R235: library part CMP-03412-022181-1, "RES SMD 11K OHM 0.1% 1/10W 0603", Manufacturer=Yageo, Manufacturer Part Number=RT0603BRC0711KL, Package=RT0603, Power Rating=0.1W, Resistance=11KΩ, Temperature="-55°C to +155°C", Temperature Coefficient="15 ppm/°C", Temperature Range High=+155°C, Temperature Range Low=-55°C, Tolerance=0.001, Voltage Rating=75V
R228 R229 R249 R251: library part CMP-1011-00293-2, Manufacturer="Yageo / Phycomp", Part Number=RC0402FR-0712R1L
R230 R234: library part CMP-2002-08208-2, "RES Thick Film, 14.3kΩ, 1%, 0.063W, 100ppm/°C, 0402 / CRCW040214K3FKED", Case Code (Imperial)=0402, Case Code (Metric)=1005, Max Operating Temperature=155°C, Max Power Dissipation=63mW, Min Operating Temperature=-55°C, Package Quantity=10, Resistance=14.3kR, Temperature Coefficient=100ppm/°C, Tolerance=1%, Voltage Rating=50V
R242: library part CMP-03412-024188-2, "RES 620Ω 1.00% 0.1W 0603", Case Code (Imperial)=0603, Case Code (Metric)=1608, Max Operating Temperature=155°C, Max Power Dissipation=100mW, Min Operating Temperature=-55°C, Resistance=620R, Resistor Type="Thick Film", Temperature Coefficient=100ppm/°C, Tolerance=1%, Voltage Rating=50V, Working Voltage=75V
R250 R252 R257 R259 R261 R262: library part CMP-02407-008912-1, "RES SMD 1.2K OHM 1% 1/10W 0402", LCSC=C2123409
R253: library part CMP-26527-000011-1, "RES 0 OHM JUMPER 1/10W 0603", Manufacturer=Stackpole, Manufacturer Part Number=RMCF0603ZT0R00, Package=RMCF0603, Power Rating=0.1W, Resistance=0mΩ, Temperature="-55°C to +155°C", Temperature Range High=+155°C, Temperature Range Low=-55°C, Voltage Rating=75V
R254 R268: library part CMP-1011-00734-3, "RES Thick Film, 95.3kΩ, 1%, 0.063W, 100ppm/°C, 0402 / CRCW040295K3FKED", Case Code (Imperial)=0402, Case Code (Metric)=1005, Max Operating Temperature=155°C, Min Operating Temperature=-55°C, Package Quantity=10000, Power Rating=63mW, Resistance=95.3kR, Temperature Coefficient=100ppm/°C, Tolerance=1%, Voltage Rating=50V
R255 R269: library part CMP-2002-08123-3, "RES Thick Film, 100kΩ, 1%, 0.063W, 100ppm/°C, 0402  / CRCW0402100KFKED", Case Code (Imperial)=0402, Case Code (Metric)=1005, Max Operating Temperature=155°C, Max Power Dissipation=63mW, Min Operating Temperature=-55°C, Package Quantity=10000, Resistance=100kR, Temperature Coefficient=100ppm/°C, Tolerance=1%, Voltage Rating=50V
R256: library part CMP-03412-037842-1, "RES 2kΩ 1.00% 0.1W 0603", Case/Package=0603, Resistance=2kR, Tolerance=1%
R258 R260: library part CMP-03412-001285-1, "RES SMD 332 OHM 0.1% 1/10W 0603", Manufacturer=Yageo, Manufacturer Part Number=RT0603BRE07332RL, Package=RT0603, Power Rating=0.1W, Resistance=332Ω, Temperature="-55°C to +155°C", Temperature Coefficient="50 ppm/°C", Temperature Range High=+155°C, Temperature Range Low=-55°C, Tolerance=0.001, Voltage Rating=75V
R264 R265: library part CMP-03412-047301-1, "RES 0Ω 5.00% 0.1W 0603", Case/Package=0603, Resistance=0mR, Tolerance=5%
R266 R270: library part CMP-02407-011830-1, "30K 0603 / MCT0603MC3002FP500", Case=0603
R267 R271: library part CMP-2002-00113-1, "CRCW040259K0FKED", Manufacturer="Vishay Dale"
R273 R277 R283: library part CMP-2002-01682-1, "TNPW040210K0DEED", Manufacturer="Vishay BCcomponents"
R294: library part CMP-2001-03865-2, "RES Thick Film, 39.2kΩ, 1%, 0.125W, 100ppm/°C, 0805", Case Code (Imperial)=0805, Case Code (Metric)=2012, Max Operating Temperature=155°C, Max Power Dissipation=125mW, Min Operating Temperature=-55°C, Package Quantity=10, Resistance=39.2kR, Temperature Coefficient=100ppm/°C, Tolerance=1%, Voltage Rating=150V
R295: library part CMP-2002-08314-3, "63mW Thick Film Resistors 75V ±1% ±100ppm/℃ 1MΩ 0402 Chip Resistor - Surface Mount ROHS", Case Code (Imperial)=0402, Max Operating Temperature=155°C, Max Power Dissipation=63mW, Min Operating Temperature=-55°C, Ratings=AEC-Q200, Resistance=1MΩ, Temperature Coefficient=100ppm/°C, Tolerance=1%, Voltage Rating=50V
R296: library part CMP-03412-015018-2, "RES 86.6kΩ ±1% 0.063W 0402", Case Code (Imperial)=0402, Case Code (Metric)=1005, Max Operating Temperature=155°C, Max Power Dissipation=63mW, Min Operating Temperature=-55°C, Power Rating=62.5mW, Resistance=86.6kR, Resistor Type="Thick Film", Temperature Coefficient=100ppm/°C, Tolerance=1%, Voltage Rating=50V
R297: library part CMP-26527-004936-1, "4.75kΩ ±1% 0.25W 0805 High Power Anti-Sulfur Thin Film Chip Resistor", Case Code (Imperial)=0805, Case Code (Metric)=2012, Max Operating Temperature=155°C, Max Power Dissipation=250mW, Min Operating Temperature=-55°C, Resistance=4.75kR, Resistor Type="Thin Film", Temperature Coefficient=100ppm/°C, Tolerance=1%
R298: library part CMP-2002-00118-4, "RES Thick Film, 5.23kΩ, 1%, 0.063W, 100ppm/°C, 0402", Case Code (Imperial)=0402, Case Code (Metric)=1005, Max Operating Temperature=155°C, Max Power Dissipation=63mW, Min Operating Temperature=-55°C, Package Quantity=10, Resistance=5.23kR, Temperature Coefficient=100ppm/°C, Tolerance=1%, Voltage Rating=50V
R299: library part CMP-009-00008-5, "1W 2mΩ Current Sense Resistor ±1% ±50ppm/℃ 1206 Current Sense Resistors / Shunt Resistors ROHS", Case/Package=1206, Max Operating Temperature=155°C, Min Operating Temperature=-55°C, Power=1W, Tolerance=0.05%, Voltage Rating=200V
R300: library part CMP-2002-08205-3, "RES Thick Film, 147kΩ, 1%, 0.063W, 100ppm/°C, 0402", Case Code (Imperial)=0402, Case Code (Metric)=1005, Max Operating Temperature=155°C, Max Power Dissipation=63mW, Min Operating Temperature=-55°C, Package Quantity=10, Resistance=147kR, Resistance Tolerance=1%, Resistor Type="Thick Film", Temperature Coefficient=100ppm/°C, Voltage Rating=50V
R301 R304: library part CMP-03412-029433-1, "RES SMD 2.2K OHM 1% 1/20W 0201", Manufacturer=Yageo, Package=RT0201, Power Rating=0.05W, Resistance=2.2KΩ, Temperature="-55°C to +125°C", Temperature Coefficient="50 ppm/°C", Temperature Range High=+125°C, Temperature Range Low=-55°C, Tolerance=0.01, Voltage Rating=25V
R302: library part CMP-03412-004791-1, "RES SMD 9.76K OHM 1% 1/8W 0805", Manufacturer=Yageo, Package=RT0805, Power Rating=0.125W, Resistance=9.76KΩ, Temperature="-55°C to +155°C", Temperature Coefficient="50 ppm/°C", Temperature Range High=+155°C, Temperature Range Low=-55°C, Tolerance=0.0001, Voltage Rating=150V
R334: library part RSMT0215, Manufacturer 1="TE Connectivity", Manufacturer 2=Vishay, Manufacturer Part Number 1=1622827-1, Manufacturer Part Number 2=CRCW0603100KFKEA, Operating Temperature="-55C to +155C", Package=0603, Power=1/10W, Supplier Part Number 1=A106046CT-ND, Temperature Coefficient=100ppm/C, Tolerance=1%, Voltage=75V
R335: library part RSMT1049, Current=1A, Manufacturer 1="Stackpole Electronics Inc", Manufacturer 2=Yageo, Manufacturer Part Number 1=RMCF0603FT15K0, Manufacturer Part Number 2=RC0603FR-0715KL, Operating Temperature="-55C to +155C", Package=0603, Power=1/10W, Supplier Part Number 1=RMCF0603FT15K0CT-ND, Temperature Coeffcient=100ppm/C, Tolerance=1%, Voltage=50V
R398 R399 R401: library part RSMT1100, Manufacturer 1=Yageo, Manufacturer Part Number 1=RC0402FR-07330RL, Package=0402, Power=1/16W, Supplier Part Number 1=311-330LRTR-ND, Tolerance=1%
R402: library part RES2380, Manufacturer 1="Panasonic Electronic Components", Manufacturer 2="KOA Speer", Manufacturer Part Number 1=ERJ-2RKF6041X, Manufacturer Part Number 2=RK73H1ETTP6041F, Package=0402, Power=1/10W, Supplier Part Number 1=P6.04KLCT-ND, Tolerance=1%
